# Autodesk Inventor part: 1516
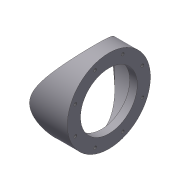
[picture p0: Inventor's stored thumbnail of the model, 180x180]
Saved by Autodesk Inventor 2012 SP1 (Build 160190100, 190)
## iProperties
Created: 2012-03
Part Number: 1516
Material: Aluminum-6061
Document SubType Name: Modeling
Designer: jdh
Mass: 550.467 g
Surface Area: 373.169 cm^2
Volume: 203.124 cm^3
Density: 2.71 g/cm^3
Author: jdh
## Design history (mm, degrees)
sketch "Sketch1"
  geometry: C1 r 69.85 at (0, 0); C2 r 47.752 at (0, 0); 1 further point
  constraints: 2 centre point, 2 coincident
  dimensions: "d0" = 139.7 diameter of C1; "d15" = 95.504 diameter of C2
extrude "Extrusion1" new body sketch "Sketch1" distance "d2" = 63.5; taper "d3" = 0 deg
sketch "Sketch3"
  geometry: L1 (0, 0)-(40.938, 0); L2 (-63.5, -69.85)-(-63.5, 69.85) reference; L3 (0, -69.85)-(0, 69.85) reference; L4 (-63.5, -47.752)-(-63.5, 47.752) reference; L5 (0, 47.752)-(0, -47.752) reference; L6 (0, 69.85)-(-63.5, 69.85) reference; L7 (0, -69.85)-(-63.5, -69.85) reference; A1 r 80.962 centre (40.938, 0) between (0, 69.85) and (0, -69.85)
  constraints: 3 end point, 2 point on circle, 1 centre point, 1 horizontal
  dimensions: "d16" = 161.925 diameter of A1
extrude "Extrusion2" cut sketch "Sketch3" stored distance "d17" = 0; taper "d18" = 0 deg
sketch "Sketch4" dims "d34" = 121.92
  geometry: L1 (0, 0)-(56.32, 23.328); L2 (0, 0)-(69.85, 0); C1 r 47.752 at (0, 0); C2 r 47.752 at (0, 0) reference; C3 r 69.85 at (0, 0) reference; 2 further points
  constraints: 4 end point, 2 coincident, 1 centre point, 1 horizontal, 1 horizontal alignment, 5 other
  dimensions: "d35" = 22.5 deg angle of L2 L1
hole "Hole2" sketch "Sketch4" at (56.32, 23.328) diameter "d20" = 4.9784; stored, may be unused: countersink angle "d24" = 82 deg, drill point angle "d26" = 118 deg; dims "d21" = 7.62, "d22" = 3.0226, "d23" = 6.35, "d25" = 10.16
pattern_circular "Circular Pattern2" dims angle "d28" = 360 deg
sketch "Sketch6"
  geometry: C1 r 64.77 at (0, 0); 4 further points
  constraints: 2 vertical alignment, 1 centre point, 1 coincident, 1 other
  dimensions: "d36" = 129.54 diameter of C1
extrude "Extrusion4" cut sketch "Sketch6" distance "d37" = 50.8; taper "d38" = 0 deg
body "Solid1"
node "Projected Loop1"
node "Projected Loop2"
node "Projected Loop3"
